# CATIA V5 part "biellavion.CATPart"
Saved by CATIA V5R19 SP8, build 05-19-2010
Part number: biellavion
Bounding box of the stored display mesh (mm): x 5 to 35, y -13.968 to 13.968, z -83.968 to 143.968
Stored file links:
  C:\Users\rcousturie\Desktop\EU_thinkMotion\iao\IAO_MMS_Groupe1\flamrini\Lamrini_projet_IAO2011\Lamrini_projet_IAO2011\projet_iao_traindatterrissage\projet_iao_traindatterrissage\biellavion.CATPart
  C:\Users\rcousturie\Desktop\EU_thinkMotion\iao\IAO_MMS_Groupe1\flamrini\Lamrini_projet_IAO2011\Lamrini_projet_IAO2011\projet_iao_traindatterrissage\projet_iao_traindatterrissage\trainavion.CATProduct
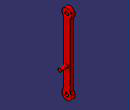
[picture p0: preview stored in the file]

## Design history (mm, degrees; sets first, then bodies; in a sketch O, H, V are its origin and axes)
Set1
  Sketch1 on yz-plane, origin (0, 0, 0), H (0, 1, 0), V (0, 0, 1)
    line L1 (-10, 120) -> (-10, -60)
    arc A1 centre (0, -70) radius 14.1421 from (-10, -60) to (10, -60) ccw
    point P3 (0, -70)
    line L2 (10, -60) -> (10, 120)
    arc A2 centre (0, 130) radius 14.1421 from (10, 120) to (-10, 120) ccw
    point P7 (10, 140)
    reference projected point E1 (0, -70) from Point1
    vertical: L1 V, L2 V
    coincidence: A2 P7, P7 L2, P3 E1
Set2
  Point1: linked copy from another document
  Line1 "axeAbis": linked copy from another document
  Line2 "axeroue": linked copy from another document
  Point2 "PointB": linked copy from another document
Body1 (main body)
  Pad1: profile Sketch1, direction (1, 0, 0), length 15, opposite side length -5
  Sketch2 on end face of Pad1, origin (15, 0, 130), H (0, 1, 0), V (0, 0, 1)
    point P1 (0, 0)
  Hole1: placed by Sketch2, at (15, 0, 130) direction (-1, 0, 0), diameter 10, through (limit type 3)
  Sketch3 on end face of Pad1, origin (15, 0, -70), H (0, 1, 0), V (0, 0, 1)
    point P1 (0, 0)
  Hole2: placed by Sketch3, at (15, 0, -70) direction (-1, 0, 0), diameter 10, through (limit type 3)
  Sketch4 on end face of Pad1, origin (15, 0, 0), H (0, 1, 0), V (0, 0, 1)
    circle A1 centre (0, 0) radius 5
    point P1 (0, 0)
    reference projected point E1 (0, 0) from Point2
    radius A1 = 5
    coincidence: P1 E1
  Pad2: profile Sketch4, direction (1, 0, 0), length 20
